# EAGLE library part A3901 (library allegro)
Dual Full Bridge Low Voltage Motor Driver Source: www.allegromicro.com .. 3901.pdf
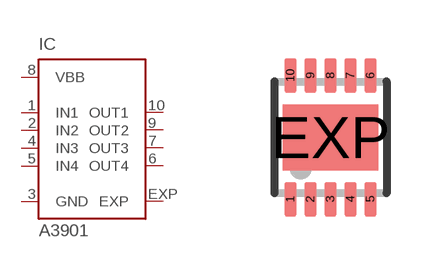
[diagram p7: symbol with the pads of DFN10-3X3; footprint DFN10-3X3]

Designator prefix IC

## A3901 (MPN: A3901SEJTR-T; OC_FARNELL: 1651947; OC_NEWARK: 87K3379)  [DFN10-3X3]
1  IN1  in
2  IN2  in
3  GND  pwr
4  IN3  in
5  IN4  in
6  OUT4  out
7  OUT3  out
8  VBB  pwr
9  OUT2  out
10  OUT1  out
EXP  EXP  pas

## Footprint DFN10-3X3 (pad centres in mm)
Package EJ, 10-contact DFN (3mm × 3mm) Source: www.allegromicro.com .. 3901.pdf
smd 0.3 x 0.85: 1 -1,-1.55; 2 -0.5,-1.55; 3 0,-1.55; 4 0.5,-1.55; 5 1,-1.55; 6 1,1.55; 7 0.5,1.55; 8 0,1.55; 9 -0.5,1.55; 10 -1,1.55
smd 2.38 x 1.65: EXP 0,0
